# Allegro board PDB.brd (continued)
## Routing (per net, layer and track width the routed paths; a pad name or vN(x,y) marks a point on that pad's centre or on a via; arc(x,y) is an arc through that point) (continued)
P12V_RISER4: length 10.2
  TOP w0.254: PU14.2 125.52,56.23 125.67,56.38 128.02,56.38 R207.1 ; v1(123.28,56.12) 123.02,56.38 121.1,56.38 120.95,56.23 PU13.2
  BOTTOM w0.254: v1(123.28,56.12) 123.54,56.38 124.25,56.38 R206.1
  vias: v1(119.46,52.49) v1(119.46,51.48) v1(119.46,50.46) v1(119.51,49.42) v1(119.63,48.27) v1(120.47,52.49) v1(120.47,51.48) v1(120.47,50.46) v1(120.5,49.34) v1(120.6,48.3) v1(121.49,51.48) v1(121.49,50.46) v1(121.51,49.34) v1(121.54,48.27) v1(122.05,52.47) v1(122.5,51.48) v1(122.5,50.46) v1(122.56,49.29) v1(123.19,54.62) v1(123.25,53.31) v1(123.52,52.49) v1(123.52,51.48) v1(123.52,50.46) v1(124.54,52.49) v1(124.54,51.48) v1(124.54,50.46) v1(125.55,52.49) v1(125.55,51.48) v1(126.62,52.47) v1(126.62,51.45) v1(127.94,55.06) v1(127.94,54.05) v1(141.99,52.72) v1(142.62,54.62) v1(142.62,53.61) v1(148.18,52.44) v1(148.26,53.86) v1(149.86,54.62) v1(149.86,53.48) v1(149.86,52.47) v1(160.25,51.22) v1(163.25,51.22) v1(164.45,50.05) v1(164.82,47.56) v1(166.75,47.51) v1(168.15,49.8) v1(170.56,50.84) v1(172.85,44.97) v1(178.31,44.47) v1(179.83,44.47) v1(180.85,44.47) v1(182.12,44.47) v1(183.14,44.47)
P12V_RISER5: length 11.8
  TOP w0.254: PU15.2 124.51,91.66 124.36,91.8 124.36,94.38 124.71,94.73 125.36,94.73 R211.1 ; v1(124.62,89.26) 124.36,89 124.36,87.08 124.51,86.93 PU16.2
  BOTTOM w0.254: v1(124.62,89.26) 124.36,89.52 124.36,90.48 R210.1
  vias: v1(125.68,89.23) v1(126.7,89.23) v1(127.79,89.23) v1(128.4,91.45) v1(128.42,90.16) v1(128.42,89.35) v1(128.4,87.01) v1(128.5,88.52) v1(129.31,89.6) v1(129.26,88.41) v1(129.51,87.63) v1(129.51,86.61) v1(129.74,88.97) v1(130.05,92.34) v1(130.18,93.28) v1(130.53,88.52) v1(130.53,87.63) v1(130.53,86.61) v1(130.56,92.75) v1(130.56,91.71) v1(130.56,89.17) v1(131.14,93.08) v1(131.14,92.32) v1(131.55,87.63) v1(131.7,86.63) v1(131.95,93.11) v1(131.95,92.34) v1(132.11,88.2) v1(132.56,87.63) v1(132.69,86.55) v1(133.58,87.63) v1(133.63,86.55) v1(133.73,89.04) v1(138.33,87.29) v1(139.52,87.26) v1(140.64,92.6) v1(140.56,87.26) v1(142.57,88.33) v1(142.77,86.98) v1(143.71,86.98) v1(143.76,93.04) v1(144.17,91.12) v1(146.69,89.8) v1(147.07,90.69) v1(147.19,92.98) v1(148.34,91.45) v1(148.34,90.69) v1(148.34,89.8) v1(158.24,85.74) v1(159.26,85.74) v1(160.27,85.74) v1(161.29,85.74) v1(162.31,85.74)
P12V_STBY: length 46.1
  TOP w0.381: R180.1 110.03,6.67 v1(110.16,6.54) ; R200.1 158.86,26.58 v1(159.11,26.32)
  VCC1 w0.381: v1(170.59,112.41) 170.92,112.41 172.92,110.4 172.92,109.74 172.03,108.85 168.96,108.85 168.29,108.18 168.29,106.2 167.51,105.42 167.51,100.22 165.34,98.04 159.77,98.04 v1(158.32,99.49)
  BOTTOM w0.305: v1(170.59,112.41) 170.48,112.31 PR1708.1
  BOTTOM w0.381: v1(169.78,25.51) 168.97,26.32 v1(159.11,26.32) ; PC851.1 169.63,24.67 v1(169.78,24.82) ; PR708.1 163.07,12.84 v1(163.58,12.33)
  vias: v1(110.16,5.53) v1(111.18,6.54) v1(111.18,5.53) v1(112.19,6.54) v1(112.19,5.53) v1(113.21,6.54) v1(113.21,5.53) v1(157.63,100.89) v1(157.63,100.18) v1(157.63,99.49) v1(158.29,100.89) v1(158.32,100.18) v1(169.16,48.78) v1(169.93,47.51) v1(169.93,46.5) v1(170.31,12.21) v1(170.5,25.51) v1(170.5,24.85) v1(171.45,11.57) v1(171.45,10.68) v1(173.99,83.96) v1(173.99,83.2) v1(173.99,82.44)
P12V_SW_PSU: length 134.3
  TOP w0.254: PU13.1 120.95,56.89 121.08,56.76 123.03,56.76 v1(123.28,57.01) ; PU17.1 154.1,68.42 155.92,68.42 156.1,68.59 156.1,71.07 v1(155.95,71.22) ; R182.2 135,24.97 132.72,24.97 132.59,25.1 PU10.1 ; v1(130.34,25.22) 130.1,24.97 128.14,24.97 128.02,25.1 PU11.1 ; PU15.1 123.85,91.66 123.98,91.78 123.98,94.53 124.56,95.11 125.27,95.11 R209.2 ; v1(123.73,89.26) 123.98,89.01 123.98,87.06 123.85,86.93 PU16.1 ; PU14.1 125.52,56.89 125.65,56.76 127.94,56.76 R203.2
  TOP w0.381: R198.1 168.13,99.44 165.51,96.81 165.51,93.26 v1(163.96,91.71) ; PR25.1 169.56,36.84 146.94,36.84 145.29,35.19 137.97,35.19 136.47,33.7 ; 112.52,31.51 112.65,31.38 PR1045.1 ; PR1048.1 109.75,31.41
  BOTTOM w0.254: v1(123.73,89.26) 123.9,89.43 123.9,90.44 123.67,90.67 R208.2 ; R201.2 131.5,25.28 131.27,25.05 130.52,25.05 v1(130.34,25.22) ; v1(155.95,71.22) 156.06,71.33 156.06,73.76 157.06,74.77 176.97,74.77 C96.1 177.31,74.82 178.07,74.82 C50.1 178.59,74.67 179.81,74.67 U18.8 ; v1(123.28,57.01) 123.45,56.83 124.21,56.83 124.44,57.07 R202.2
  BOTTOM w0.381: v1(151.51,82.44) 152.13,83.05 153.44,83.05 162.09,91.71 v1(163.96,91.71)
  vias: v1(101.88,80.28) v1(101.96,76.06) v1(101.98,75.2) v1(101.98,64.66) v1(101.98,63.9) v1(101.96,62.93) v1(101.98,40.27) v1(101.98,39.13) v1(102.21,82.16) v1(102.82,75.07) v1(103,39.64) v1(103.12,79.44) v1(103.12,76.06) v1(103.12,74.23) v1(103.12,71.9) v1(103.12,70.98) v1(103.12,68.52) v1(103.12,65.27) v1(103.12,63.31) v1(103.23,45.76) v1(103.25,59.65) v1(103.25,48.73) v1(103.38,82.16) v1(103.38,56.99) v1(103.38,51.14) v1(103.38,44.34) v1(103.48,54.98) v1(103.5,53.99) v1(103.48,53.02) v1(103.89,39.64) v1(104.11,43.47) v1(104.11,42.2) v1(104.39,79.44) v1(104.39,76.06) v1(104.39,74.23) v1(104.39,68.52) v1(104.39,65.27) v1(104.39,63.31) v1(104.52,71.13) v1(104.52,59.65) v1(104.5,54.98) v1(104.5,53.02) v1(104.52,48.73) v1(104.65,82.16) v1(104.65,56.99) v1(104.65,51.14) v1(104.78,78.25) v1(104.9,39.64) v1(105.54,68.52) v1(105.66,65.27) v1(105.66,63.31) v1(105.66,54.98) v1(105.66,53.02) v1(105.79,76.19) v1(105.79,74.23) v1(105.92,71.19) v1(106.05,78.25) v1(106.17,82.36) v1(106.93,65.27) v1(106.93,63.31) v1(106.93,54.98) v1(106.93,53.02) v1(107.19,78.25) v1(107.19,71.19) v1(107.31,76.19) v1(107.31,74.23) v1(107.44,82.36) v1(108.2,54.98) v1(108.2,53.02) v1(108.58,78.25) v1(108.56,65.19) v1(108.56,63.24) v1(108.92,76.21) v1(108.92,74.26) v1(108.99,46.32) v1(109.45,44.87) v1(109.45,43.6) v1(109.45,42.33) v1(109.47,54.98) v1(109.47,53.02) v1(109.47,39.64) v1(109.98,65.19) v1(109.98,63.24) v1(110.34,76.21) v1(110.34,74.26) v1(110.36,77.87) v1(110.36,75.33) v1(110.62,64.28) v1(111.1,54.9) v1(111.1,52.95) v1(111.91,49.21) v1(111.89,48.48) v1(112.52,54.9) v1(112.52,52.95) v1(116.97,91.45) v1(116.97,90.44) v1(116.97,89.42) v1(117.09,93.49) v1(117.09,92.47) v1(117.98,93.49) v1(117.98,92.47) v1(117.98,91.45) v1(117.98,90.44) v1(117.98,89.42) v1(117.98,88.41) v1(118.62,59.87) v1(118.62,58.85) v1(118.62,57.84) v1(119,93.49) v1(119,92.47) v1(119,91.45) v1(119,90.44) v1(119,89.42) v1(119,88.41) v1(119,87.52) v1(119.63,63.67) v1(119.63,62.65) v1(119.63,61.76) v1(119.63,60.75) v1(119.89,89.68) v1(119.89,87.01) v1(119.89,86.25) v1(120.02,93.49) v1(120.02,92.47) v1(120.02,91.45) v1(120.02,90.44) v1(120.02,87.9) v1(120.32,98.01) v1(120.32,96.99) v1(120.4,95.95) v1(120.6,89.23) v1(120.65,63.67) v1(120.65,62.65) v1(120.65,61.76) v1(120.65,60.75) v1(121.03,93.99) v1(121.34,98.01) v1(121.34,96.99) v1(121.41,95.95) v1(121.62,89.23) v1(121.67,63.67) v1(121.67,62.65) v1(121.67,61.76) v1(122.05,93.99) v1(122.05,60.85) v1(122.35,98.01) v1(122.35,96.99) v1(122.43,95.95) v1(122.63,89.23) v1(122.56,63.67) v1(122.68,61.76) v1(122.81,62.65) v1(123.06,93.99) v1(123.19,58.82) v1(123.28,60.01) v1(123.57,63.67) v1(123.7,61.76) v1(123.7,60.75) v1(123.83,62.65) v1(124.71,61.76) v1(124.71,60.75) v1(124.84,63.51) v1(124.84,62.65) v1(125.73,61.76) v1(125.78,62.78) v1(125.86,63.51) v1(126.62,60.85) v1(126.75,61.76) v1(126.8,62.78) v1(126.87,63.51) v1(127.48,31.08) v1(127.51,29.73) v1(127.56,62.78) v1(127.56,61.76) v1(127.56,60.75) v1(127.89,63.51) v1(127.88,28.99) v1(128.4,31.26) v1(128.5,30.19) v1(128.57,62.78) v1(128.57,61.76) v1(128.57,60.75) v1(129.01,31.97) v1(129.46,60.62) v1(129.46,59.6) v1(129.46,58.59) v1(129.51,31.21) v1(129.51,30.19) v1(129.51,29.17) v1(130.02,31.97) v1(130.3,27.98) v1(130.3,26.94) v1(130.53,31.21) v1(130.53,30.19) v1(130.53,29.17) v1(130.61,60.87) v1(130.61,59.86) v1(131.06,32.02) v1(131.55,31.21) v1(131.55,30.19) v1(131.55,29.17) v1(132.38,28.99) v1(132.56,31.21) v1(132.56,30.19) v1(133.1,32.02) v1(133.58,31.21) v1(133.58,30.19) v1(133.58,29.17) v1(134.54,31.99) v1(134.59,31.21) v1(134.59,30.19) v1(134.59,29.17) v1(135.43,28.39) v1(135.61,31.21) v1(135.61,30.19) v1(135.61,29.17) v1(136.02,32.02) v1(136.35,29.48) v1(136.4,28.72) v1(136.63,31.21) v1(136.63,30.19) v1(151.1,73.04) v1(151.1,72.28) v1(151.1,71.52) v1(151.1,70.75) v1(151.1,69.99) v1(151.1,69.23) v1(151.1,68.47) v1(151.1,67.71) v1(151.1,66.94) v1(151.87,73.04) v1(151.87,72.28) v1(151.87,71.52) v1(151.87,70.75) v1(151.87,69.99) v1(151.87,69.23) v1(151.89,68.47) v1(151.87,67.71) v1(151.87,66.94) v1(151.87,66.18) v1(152.63,73.04) v1(152.63,72.28) v1(152.63,71.52) v1(152.63,70.75) v1(152.7,66.13) v1(152.7,65.37) v1(153.39,73.04) v1(153.39,72.28) v1(153.39,71.52) v1(153.39,70.75) v1(153.47,66.13) v1(153.47,65.37) v1(154.15,73.04) v1(154.15,72.28) v1(154.15,71.52) v1(154.15,70.75) v1(154.23,66.13) v1(154.23,65.37) v1(154.91,72.28) v1(154.91,71.52) v1(154.91,70.75) v1(154.99,66.13)
ADM1278_ADR1: length 3.9
  TOP w0.203: v1(114.12,20.45) 114.11,20.44 113.69,20.44 113.31,20.81 PU12.7
  BOTTOM w0.216: v1(114.12,20.45) 114.12,19.95 114.3,19.78 v2(114.3,19.62) 114.3,19.47 113.59,18.76 R11.2
ADM1278_ADR2: length 3.9
  TOP w0.216: PU12.8 114.23,21.29 114.3,21.22 v1(114.4,21.22)
  BOTTOM w0.216: v1(114.4,21.22) 114.4,21.17 114.96,20.61 114.96,18.78 R12.1
AT24C64_ADD0: length 7.6
  TOP w0.216: v3(174.09,91.68) 172,91.68 171.66,92.02 R118.2 171.03,91.61 169.65,91.61 169.37,91.88 R119.1 U3.1
AT24C64_ADD1: length 4.9
  TOP w0.216: R120.2 171.66,93.16 171.37,92.88 v1(169.77,92.88) 169.37,93.28 R121.1 U3.2
AT24C64_ADD2: length 5.8
  TOP w0.216: U3.3 R123.1 169.37,95.01 v3(170.66,96.3) 171.66,95.3 R122.2
BMC_NODE_ID_0: length 64.4
  TOP w0.216: C134.1 v1(18.16,89.22) L2.1
  BOTTOM w0.216: J5.3 64.45,107.52 64.45,105.59 63.33,104.47 24.46,104.47 23.13,103.13 23.13,91.65 21.3,89.83 18.77,89.83 v1(18.16,89.22)
BMC_NODE_ID_0_R: length 2.9
  TOP w0.216: J8.3 18.16,84.94 L2.2
BMC_NODE_ID_1: length 61.8
  TOP w0.216: L12.2 v1(16.89,89.24) C145.1
  BOTTOM w0.216: J5.4 61.98,104.89 24.29,104.89 22.71,103.31 22.71,91.83 21.13,90.25 17.89,90.25 v1(16.89,89.24)
BMC_NODE_ID_1_R: length 5.4
  TOP w0.216: J8.4 17.27,83.83 17.27,87.35 L12.1
BMC_NODE_ID_2: length 56.6
  TOP w0.216: L16.2 v1(8,89.24) C139.1
  VCC1 w0.213: v1(8,89.24) 8,89.32 8.47,89.79 12.51,89.79 13.86,91.14 13.86,93.44 16.28,95.86 16.28,97.83 23.86,105.4 52.49,105.4 J5.14
BMC_NODE_ID_2_R: length 5.7
  TOP w0.216: L16.1 8,86.81 9.17,85.64 9.17,83.79 J8.14
BMC_NODE_ID_3: length 57.5
  TOP w0.216: 6.73,89.17 L6.1 6.71,88.56 v1(6.71,89.14) 6.73,89.17 ; 6.73,89.17 C129.1
  VCC1 w0.213: v1(6.71,89.14) 6.71,89.28 8.05,90.62 10.59,90.62 11.3,91.33 11.3,92.06 14.2,94.97 14.2,97.4 23.04,106.24 41.72,106.24 44.87,109.39 50.58,109.39 J5.15
BMC_NODE_ID_3_R: length 3.1
  TOP w0.216: L6.2 6.75,87.72 6.75,85.37 J8.15
BMC_NODE_ID_4: length 61.9
  TOP w0.216: C138.1 v1(5.46,89.17) L17.2
  VCC1 w0.213: v1(5.46,89.17) 5.74,89.17 7.42,90.85 7.42,91.58 8.06,92.22 10.37,92.22 10.87,92.22 13.79,95.14 13.79,97.57 22.87,106.65 41.55,106.65 44.7,109.8 51.5,109.8 52.45,108.86 52.45,107.36 J5.16
BMC_NODE_ID_4_R: length 6.8
  TOP w0.216: L17.1 v1(5.46,86.15)
  BOTTOM w0.216: J8.16 7.26,83.89 7.26,85.59 6.71,86.15 v1(5.46,86.15)
BMC_NODE_ID_5: length 55.8
  TOP w0.216: L7.1 C128.1 4.58,89.89 4.72,90.03 4.72,92.22 7.06,94.55 12.45,94.55 14.91,97.01 v1(14.91,97.25)
  VCC1 w0.213: v1(14.91,97.25) 15.11,97.25 23.68,105.82 42.03,105.82 44.65,108.44 J5.17
BMC_NODE_ID_5_R: length 2.9
  TOP w0.216: J8.17 4.19,84.91 L7.2
CSOUT_N: length 5.6
  TOP w0.216: R164.2 113.61,30.57 v4(113.79,30.75)
  BOTTOM w0.216: C60.1 R167.1 113.77,30.73 v4(113.79,30.75) 114.71,31.67 U19.2
CSOUT_P: length 8.9
  BOTTOM w0.216: U19.3 116.38,32.32 116.87,32.81 116.87,33.42 116.33,33.95 115.34,33.95 v2(114.96,34.33) 114.58,33.95 113.18,33.95 113.03,33.8 C59.1 R166.1 R165.2
EMC1413_ADDR: length 3.3
  TOP w0.216: v1(98.42,100.09) 98.42,100.75 98.11,101.06 U2.7
  BOTTOM w0.216: v1(98.42,100.09) 97.94,100.57 R124.2
EMC1413_ALERT_N: length 5.6
  TOP w0.216: v1(99.64,100.6) 99.29,100.6 98.32,101.56 U2.8
  BOTTOM w0.216: R46.2 98.65,101.59 v1(99.64,100.6)
EN_HSC_IN: length 102.7
  TOP w0.216: v1(148.23,35.89) 148.64,35.89 R212.1 149.46,34.43 R183.1 ; U1.6 105.62,105.64 v1(104.9,104.92)
  BOTTOM w0.216: R185.2 104.78,105.04 v1(104.9,104.92) 105.54,104.28 105.54,101.8 105.99,101.35 105.99,92.14 116.57,81.55 116.57,76.05 123.45,69.17 136.9,69.17 145.63,60.44 145.63,52.33 149.44,48.52 149.44,37.19 148.23,35.98 v1(148.23,35.89)
EN_HSC_IN_R: length 1.7
  TOP w0.216: U12.2 148.08,33.29 148.23,33.44 v1(148.31,33.44) 148.34,33.44 148.51,33.27 R183.2
EN_HSC_P2V_IN_N: length 14.9
  VCC1 w0.213: J20.1 121.28,20.08 v1(119.84,20.08)
  BOTTOM w0.216: v1(119.84,20.08) 119.94,19.99 119.94,19.05 119.4,18.51 117.02,18.51 116.59,18.94 116.59,19.41 116.2,19.8 Q19.5 Q19.6 115.7,20.62 115.7,22.49 115.82,22.62 R158.1 R157.2
EN_HSC_P12V_IN: length 4.6
  TOP w0.254: PR1014.1 R13.2 119.13,19.17 v1(119.25,19.29)
  BOTTOM w0.216: Q19.3 118.88,19.15 119.02,19.29 v1(119.25,19.29)
EN_HSC_P12V_IN_BUF: length 2.1
  TOP w0.216: R184.1 145.08,34.58 v1(145.61,34.58) U12.4
EN_HSC_P12V_IN_BUF_R1: length 41.4
  TOP w0.216: R184.2 143.11,33.92 142.6,34.43 v1(142.49,34.43)
  BOTTOM w0.216: v1(142.49,34.43) 140.61,34.43 138.6,36.45 126.51,36.45 121.12,31.06 121.12,27.1 119.84,25.82 119.84,21.27 118.36,19.8 Q19.2 117.47,19.8 116.19,21.09 R163.1
EN_HSC_P12V_STBY: length 3.8
  TOP w0.216: U20.4 105.8,5.02 105.93,5.15 v1(106.4,5.15) 106.91,5.65 C107.1 R152.2 R153.1
EN_P3V3_D1G2: length 3.8
  TOP w0.216: PQ2.5 166.64,33.92 PR23.2 PR24.1 166.76,33.27 v1(167.13,33.27) PQ2.6
EN_P3V3_D2: length 2.9
  TOP w0.216: PR26.1 171.06,34.57 170.83,34.57 v1(170.32,35.08) 169.81,34.57 PQ2.3 169.73,35.49 PR25.2
EN_P3V3_G1: length 2.4
  TOP w0.216: PR22.2 168.94,35.57 v1(168.94,35.02) 168.94,34.28 169.29,33.92 PQ2.2
EN_P3V3_GATE: length 5.2
  TOP w0.381: PR26.2 171.75,35.37 v1(171.78,35.37) PC34.1 172.64,36.23 PC28.2 174.68,36.23 175.01,35.9 PQ3.4
FAN_OC_ALERT: length 8.5
  BOTTOM w0.216: R4.1 186.99,81.66 v2(187.3,81.35) 187.3,81.09 186.29,80.08 R29.1 186.29,79.64 186.06,79.41 R145.2 185.1,78.77 R147.1 185.04,78.46 184.08,77.5 183.65,77.5 183.64,77.51 Q16.5
FAN_OC_ALERT_N: length 3.6
  BOTTOM w0.216: Q2.6 186.2,86.62 186.82,87.24 v2(187.35,87.24) 187.4,87.19 R3.2
FAN_OC_ALERT_R: length 5.2
  BOTTOM w0.216: R4.2 186.19,82.78 185.55,83.42 Q2.2 Q2.5 185.55,87.06 v2(185.32,87.29)
FAN_OC_ALERT_R1_N: length 4.4
  BOTTOM w0.216: R6.1 183.65,84.7 v2(182.54,84.7) 182.54,84 182.67,83.88 Q2.3
FAN_OC_ALERT_R_N: length 106.9
  TOP w0.216: v1(111.46,112.51) 111,112.05 111,107.2 111.91,106.29 U1.20
  VCC1 w0.213: v1(111.46,112.51) 111.61,112.66 141.99,112.66 144.27,110.38 144.27,100.6 147.19,97.68 155.96,97.68 156.54,97.09 175.37,97.09 175.42,97.14 v1(176.2,97.14)
  BOTTOM w0.216: R10.2 R3.1 187.69,85.16 187.96,85.43 187.96,87.62 185.75,89.83 180.06,89.83 176.2,93.69 v1(176.2,97.14)
FAN_OC_CLEAR: length 115.3
  TOP w0.216: v1(110.21,112.49) 110.44,112.26 110.44,104.48 108.34,102.39 U1.11
  VCC1 w0.213: v1(110.21,112.49) 110.8,113.08 142.16,113.08 144.69,110.55 144.69,100.77 147.37,98.09 156.13,98.09 156.7,97.53 175.21,97.53 v1(175.67,97.98)
  BOTTOM w0.216: Q16.2 179.58,77.51 R20.1 177.4,77.25 v2(176.15,78.5) 175.01,79.64 175.01,97.32 v1(175.67,97.98)
HS_P12V_RSEN: length 32.6
  TOP w0.254: PU21.2 89.6,60.91 89.45,61.06 89.45,63.41 PR1029.2 ; R189.2 91.39,40.31 89.63,40.31 89.45,40.49 89.45,42.84 R139.2 ; PR1031.2 89.45,77.13 89.45,74.78 89.6,74.63 PU19.2 ; PR1027.2 89.45,49.7 89.45,47.35 89.6,47.2 91.34,47.2 ; PU20.2 89.6,67.77 89.45,67.92 89.45,70.27 PR1030.2 ; PR1032.2 89.45,83.86 89.45,81.64 89.6,81.49 PU18.2 ; PU22.2 89.6,54.06 89.45,54.2 89.45,56.56 PR1028.2
  vias: v1(91.14,79.21) v1(91.14,78.45) v1(91.14,77.69) v1(91.14,76.93) v1(91.14,72.35) v1(91.14,71.59) v1(91.14,70.83) v1(91.14,70.07) v1(91.14,65.5) v1(91.14,64.73) v1(91.14,63.97) v1(91.14,63.21) v1(91.14,58.64) v1(91.14,57.88) v1(91.14,57.11) v1(91.14,56.35) v1(91.14,51.78) v1(91.14,51.02) v1(91.14,50.26) v1(91.14,49.49) v1(91.14,44.92) v1(91.14,44.16) v1(91.14,43.4) v1(91.14,42.64) v1(91.24,37.99) v1(92.15,79.21) v1(92.15,78.45) v1(92.15,77.69) v1(92.15,76.93) v1(92.15,72.35) v1(92.15,71.59) v1(92.15,70.83) v1(92.15,70.07) v1(92.15,65.5) v1(92.15,64.73) v1(92.15,63.97) v1(92.15,63.21) v1(92.15,58.64) v1(92.15,57.88) v1(92.15,57.11) v1(92.15,56.35) v1(92.15,51.78) v1(92.15,51.02) v1(92.15,50.26) v1(92.15,49.49) v1(92.15,44.92) v1(92.15,44.16) v1(92.15,43.4) v1(92.15,42.64) v1(92.25,37.99) v1(95.53,81.24) v1(95.53,75.4) v1(95.53,69.56) v1(95.53,63.72) v1(95.53,57.88) v1(95.53,52.03) v1(95.53,46.19) v1(95.53,40.35) v1(96.55,82.26) v1(96.55,80.23) v1(96.55,76.42) v1(96.55,74.39) v1(96.55,70.58) v1(96.55,68.54) v1(96.55,64.73) v1(96.55,62.7) v1(96.55,58.89) v1(96.55,56.86) v1(96.55,53.05) v1(96.55,51.02) v1(96.55,47.21) v1(96.55,45.18) v1(96.55,41.37) v1(96.55,39.33) v1(97.56,81.24) v1(97.56,75.4) v1(97.56,69.56) v1(97.56,63.72) v1(97.56,57.88) v1(97.56,52.03) v1(97.56,46.19) v1(97.56,40.35)
HSC_P12V_AGND: length 17.9
  TOP w0.216: PU12.22 v1(111.31,27.4)
  TOP w0.305: v1(107.24,23.59) 107.16,23.59 106.73,23.15 PC1018.2 ; v1(108.31,18.84) 107.75,18.28 PC1013.2 PR1033.2 ; PR1037.2 PC1015.2 107.78,20.04 v1(108.33,20.59) ; PC1020.2 106.76,26.13 v1(107.21,25.67)
  TOP w0.381: PC1017.2 105.69,21.27 v1(105.44,21.02) ; PC1016.2 113.41,17.77 v1(112.88,17.24) 112.88,17.32 PC1010.2
  TOP w0.457: PC1011.2 117.6,23.13 117.91,22.82 v1(117.91,22.32) 117.6,22.01 PR1010.2 ; PC1012.2 109.04,17.85 v1(109.4,17.49) 110.13,17.49 PC109.2 110.45,17.8 PC1014.2 ; PR1050.2 PC1023.2 v1(111.68,29.61)
  BOTTOM w0.381: 113.28,16.52 113.67,16.52 114.55,17.41 R12.2
  vias: v1(110.79,23.84) v1(112.06,25.11) v1(112.06,22.57) v1(113.33,23.84) v2(110.03,23.18)
HSC_P12V_ALERT_N: length 2.8
  TOP w0.216: PU12.13 115.77,24.09 v3(116.05,24.37) 117.18,24.37 PR10153.2
HSC_P12V_CSOUT: length 2.5
  TOP w0.216: PU12.19 112.81,27 113.49,27.68 v1(113.72,27.68) 113.72,28.19 R164.1
HSC_P12V_DN: length 84
  TOP w0.254: v1(108.33,24.82) 108.46,24.82 108.7,24.59 PU12.27 ; PR1032.1 89.41,85.12 89.41,85.46 v1(89.56,85.61) ; PR1029.1 89.41,64.68 89.41,65.01 v1(89.56,65.17) ; v1(89.56,44.59) 89.41,44.44 89.41,44.1 R139.1 ; v1(89.56,58.31) 89.41,58.16 89.41,57.82 PR1028.1 ; v1(105.13,25.06) 105.13,25.01 105.26,24.88 105.59,24.88 PR1042.1 PC1020.1 ; v1(89.56,51.45) 89.41,51.3 89.41,50.96 PR1027.1 ; PR1031.1 89.41,78.39 89.41,78.73 v1(89.56,78.88) ; PR1030.1 89.41,71.53 89.41,71.87 v1(89.56,72.02)
  BOTTOM w0.254: v1(108.33,24.82) 108.21,24.7 107.4,24.7 107.3,24.81 105.38,24.81 v1(105.13,25.06) 104.93,24.86 103.97,24.86 103.25,25.57 103.25,27.83 98.41,32.68 96.68,32.68 92.13,37.23 90.2,37.23 89.41,38.02 89.41,44.44 v1(89.56,44.59) 89.41,44.74 89.41,51.3 v1(89.56,51.45) 89.41,51.6 89.41,58.16 v1(89.56,58.31) 89.41,58.46 89.41,65.01 v1(89.56,65.17) 89.41,65.32 89.41,71.87 v1(89.56,72.02) 89.41,72.18 89.41,78.73 v1(89.56,78.88) 89.41,79.03 89.41,85.46 v1(89.56,85.61)
HSC_P12V_DP: length 84.6
  TOP w0.254: v1(88.87,85.61) 89.03,85.46 89.03,85.12 PR1018.1 ; PR1020.1 89.03,50.96 89.03,51.3 v1(88.87,51.45) ; PR1015.1 89.03,64.68 89.03,65.01 v1(88.87,65.17) ; v1(88.87,78.88) 89.03,78.73 89.03,78.39 PR1017.1 ; v1(88.87,72.02) 89.03,71.87 89.03,71.53 PR1016.1 ; v1(105.11,24.25) 105.11,24.27 105.23,24.4 105.59,24.4 PR1041.1 PC1018.1 ; v1(108.33,24.16) 108.4,24.09 PU12.28 ; v1(88.87,44.59) 89.03,44.44 89.03,44.1 R58.1 ; v1(88.87,58.31) 89.03,58.16 89.03,57.82 PR1019.1
  BOTTOM w0.254: v1(88.87,85.61) 89.03,85.46 89.03,79.03 v1(88.87,78.88) 89.03,78.73 89.03,72.18 v1(88.87,72.02) 89.03,71.87 89.03,65.32 v1(88.87,65.17) 89.03,65.01 89.03,58.46 v1(88.87,58.31) 89.03,58.16 89.03,51.6 v1(88.87,51.45) 89.03,51.3 89.03,44.74 v1(88.87,44.59) 89.03,44.44 89.03,37.86 90.04,36.84 91.97,36.84 96.52,32.3 98.25,32.3 102.87,27.68 102.87,25.42 103.81,24.47 104.88,24.47 v1(105.11,24.25) 105.28,24.42 107.14,24.42 107.25,24.31 108.18,24.31 v1(108.33,24.16)
HSC_P12V_EN: length 6.6
  TOP w0.216: v3(115.16,19.65) 115.67,20.16 PR1014.2 116.49,20.18 PR1011.2 PR1010.1 116.49,23.08 PC1011.1 115.62,23.13 115.16,23.59 PU12.12
HSC_P12V_FAULT_N: length 153.5
  TOP w0.216: PU12.6 112.81,20.7 114.35,19.17 PR10154.2 114.81,18.42 115.7,17.54 116.61,17.54 117.03,17.96 v1(117.16,17.96) ; v1(106.93,99.84) 107.06,99.96 108.65,99.96 109.68,100.99 109.68,101.68 109.68,101.68 109.68,101.94 111,103.27 112.7,103.27 112.93,103.04 U1.15
  BOTTOM w0.216: v1(117.16,17.96) 117.23,18.02 119.51,18.02 120.36,18.87 120.36,25.64 121.54,26.82 121.54,30.88 126.69,36.03 138.1,36.03 140.34,33.8 145.8,33.8 147.19,35.19 148.46,35.19 149.86,36.59 149.86,48.7 146.05,52.51 146.05,60.62 137.08,69.59 123.62,69.59 116.99,76.22 116.99,81.73 106.41,92.31 106.41,99.31 v1(106.93,99.84)
HSC_P12V_GATE: length 0.6
  TOP w0.305: PU12.24 v1(109.73,26.39)
  vias: v2(108.43,29.48)
HSC_P12V_GATE1: length 3
  TOP w0.508: PQ101.4 v1(101.85,48.11)
  BOTTOM w0.508: v1(101.85,48.11) 101.83,48.09 PR102.1
HSC_P12V_GATE2: length 2.8
  TOP w0.508: PQ102.4 v1(101.85,42.27)
  BOTTOM w0.508: PR103.1 101.83,42.3 v1(101.85,42.27)
HSC_P12V_GATE3: length 2.7
  TOP w0.457: PQ103.4 101.58,83.16 v1(101.59,83.17)
  BOTTOM w0.508: PR104.1 101.46,83.3 v1(101.59,83.17)
HSC_P12V_GATE4: length 2.8
  TOP w0.508: v1(101.85,71.48) PQ104.4
  BOTTOM w0.508: PR105.1 101.83,71.51 v1(101.85,71.48)
HSC_P12V_GATE5: length 2.9
  TOP w0.508: PQ105.4 101.82,77.32 v1(101.85,77.36)
  BOTTOM w0.508: v1(101.85,77.36) 101.83,77.38 PR106.1
HSC_P12V_GATE6: length 2.8
  TOP w0.508: PQ106.4 v1(101.83,65.64)
  BOTTOM w0.508: PR101.1 v1(101.83,65.64)
HSC_P12V_GATE7: length 3
  TOP w0.508: v1(101.85,53.95) PQ107.4
  BOTTOM w0.508: PR1049.1 101.83,53.93 v1(101.85,53.95)
HSC_P12V_GATE8: length 3
  TOP w0.508: PQ108.4 v1(101.85,59.8)
  BOTTOM w0.508: v1(101.85,59.8) 101.83,59.77 PR107.1
HSC_P12V_ISET: length 6
  TOP w0.216: PU12.3 111.31,19.56 v1(111,19.24) 111.43,18.81 PC1014.1
  BOTTOM w0.216: v1(111,19.24) 111.02,19.27 111.18,19.27 111.4,19.5 111.4,19.6 112.16,20.35 PR1035.2 PR1036.1
HSC_P12V_ISTART: length 6.4
  TOP w0.216: PU12.4 111.81,19.7 v1(112.29,19.22) 112.39,19.12 PC1010.1
  BOTTOM w0.216: PR109.1 112.29,19.76 v1(112.29,19.22) 112.29,19.15 PR108.2
HSC_P12V_MON: length 3.3
  TOP w0.254: PR1042.2 106.76,25.03 PC1019.2 108.01,25.41 108.61,25.41 108.94,25.09 PU12.26
HSC_P12V_MOP: length 3.4
  TOP w0.254: PR1041.2 106.73,24.23 PC1019.1 107.62,23.99 108.02,23.59 PU12.29
HSC_P12V_OV: length 7.4
  TOP w0.216: PR1034.2 105.61,18.96 105.73,19.08 PR1033.1 PC1013.1 107.75,19.08 109.51,20.85 PU12.32
HSC_P12V_PSET: length 5.1
  TOP w0.216: v1(109.42,19.55) 109.42,19.88 110.31,20.77 PU12.1
  TOP w0.254: PC1012.1 109.04,19.17 v1(109.42,19.55)
  BOTTOM w0.216: PR1013.1 PR1012.2 109.61,20.06 109.42,19.88 v1(109.42,19.55)
HSC_P12V_PWGIN: length 4.4
  TOP w0.216: PR1048.2 109.75,28.59 v1(110.06,28.28) 110.2,28.14 PR1050.1 PC1023.1 111.75,28.14 111.89,28.01 111.89,27.04 111.81,26.97 PU12.21
HSC_P12V_PWRGD: length 207.2
  TOP w0.216: v1(153.03,91.45) 153.03,91.33 153.47,90.9 164.41,90.9 166.07,92.55 166.07,96.41 167.59,97.93 172.59,97.93 173.61,98.95 R15.1 ; PR22.1 167.36,36.34 156.09,36.34 v1(155.7,35.96) ; R14.2 PR10152.2 115.6,28.99 116.82,28.99 118.68,27.13 v1(122.66,27.13) ; v1(99.77,7.03) v1(102.92,7.03)
  BOTTOM w0.216: Q3.G 99.25,6.25 99.77,6.77 v1(99.77,7.03) ; v1(153.03,91.45) 153.03,91.16 154.03,90.17 154.03,88.81 151.94,86.73 148.38,86.73 145.74,84.09 138.79,84.09 137.38,82.67 137.38,74.51 151.28,60.6 151.28,52.44 155.88,47.84 155.88,36.13 v1(155.7,35.96) 155.7,34.74 154.79,33.82 150.39,33.82 149.43,32.86 146.01,32.86 145.32,32.18 140.58,32.18 137.99,34.77 127.34,34.77 122.56,29.99 122.56,27.23 v1(122.66,27.13) 122.56,27.03 122.56,26.65 121.2,25.29 121.2,17.93 119.7,16.44 116.2,16.44 114.75,14.98 107.92,14.98 106.43,13.49 106.43,7.69 105.77,7.03 v1(102.92,7.03)
HSC_P12V_PWRGD_R: length 3.3
  TOP w0.216: R14.1 114.6,27.95 v1(115.01,27.55) 114.68,27.22 114.05,27.22 113.94,27.12 113.54,27.12 113.31,26.89 PU12.18
HSC_P12V_STBY_AGND: length 0.7
  TOP w0.381: C107.2 v1(108.46,5.65)
  vias: v1(102.03,3.49) v1(102.03,2.48)
HSC_P12V_STBY_FAULT_INPUT: length 4.1
  TOP w0.216: R181.1 R180.2 106.05,5.76 v1(105.26,5.76) 105.15,5.86 U20.6
HSC_P12V_STBY_GATE: length 6.2
  TOP w0.508: v1(115.29,6.34) 115.29,6.21 115.09,6.01 R50.1 114.35,6.14 Q5.4
  BOTTOM w0.508: v1(115.29,6.34) 115.29,5.83 114.04,4.59 R49.2
HSC_P12V_STBY_GATE_R: length 10.4
  TOP w0.432: U20.5 105.8,7.64 106.58,8.42 107.34,8.42 v1(107.49,8.57)
  BOTTOM w0.508: v1(107.49,8.57) 107.52,8.6 107.57,8.6 107.7,8.48 107.7,5.35 108.2,4.84 109.21,4.84 109.46,4.59 111.52,4.59 R49.1
HSC_P12V_STBY_PWRGD: length 87.9
  TOP w0.216: v1(108.84,1.92) 108.97,1.92 109.52,2.48 R171.2 109.48,3.14 109.3,3.14 108.78,2.62 C109.1 R173.1 105.15,2.93 U20.3 ; v1(150.35,32.36) 153.8,28.92 153.8,26.94 156.08,24.65 PR702.1
  BOTTOM w0.216: v1(108.84,1.92) 108.97,2.05 108.97,2.81 110.13,3.97 114.23,3.97 116.61,6.35 116.61,8.8 117.09,9.29 117.09,15.47 117.64,16.02 119.88,16.02 121.62,17.76 121.62,25.04 123.19,26.62 123.19,30.03 127.52,34.36 137.81,34.36 140.4,31.76 145.67,31.76 145.97,32.07 147.14,32.07 147.73,31.49 149.47,31.49 v1(150.35,32.36)
HSC_P12V_STBY_RSENSE: length 4.6
  TOP w0.254: R48.2 104.83,13.02 104.57,12.77 104.57,10.5 R155.1
  vias: v3(108.99,10.4)
HSC_P12V_STBY_TIMER: length 2.7
  TOP w0.381: U20.1 103.85,5.23 103.58,5.5 102.84,5.5 102.79,5.55 ; 102.79,5.55 v1(102.77,5.58) ; 102.79,5.55 C106.1
HSC_P12V_TEMP: length 4.2
  TOP w0.305: PR1047.1 107.49,27.32 PC1021.2 108.43,27.5 v3(108.43,26.68) 108.43,26.56 109.4,25.59 PU12.25
HSC_P12V_TIMER: length 3.2
  TOP w0.216: PC1016.1 113.41,19.14 v3(112.67,19.88) 112.31,20.24 PU12.5
HSC_P12V_UV: length 6.8
  TOP w0.216: PU12.31 108.94,22.59 108.71,22.37 108.71,21.73 107.82,20.84 PC1015.1 PR1037.1 106.21,20.84 105.43,20.06 v3(105.23,20.06) 105.13,19.95 PR1038.2
HSC_P12V_VCAP: length 10.3
  TOP w0.254: PU12.2 110.81,20.25 v1(110.59,20.03)
  TOP w0.305: PC109.1 110.26,19.7 v1(110.59,20.03)
  BOTTOM w0.254: PR1035.1 110.51,20.61 PR1012.1 110.41,20.21 v1(110.59,20.03) 110.59,19.72 110.32,19.45 PR108.1 110.32,17.84 110.72,17.44 111.86,17.44 v2(112.34,17.92) 112.98,17.92 113.33,17.57 R11.1
HSC_P12V_VCC: length 6.1
  TOP w0.254: PU12.30 108.59,23.09 108.2,22.7 108.2,22.11 108.02,21.93 107.22,21.93 PC1017.1
  TOP w0.381: v1(107.57,22.8) 107.16,22.39 PC1017.1
  BOTTOM w0.381: PR1039.2 107.57,22.21 107.57,22.62
  BOTTOM w0.457: 107.57,22.62 v1(107.57,22.8)
HSC_P12V_VOUT: length 2
  TOP w0.216: PU12.20 112.31,26.82 112.34,26.85 112.34,27.42 v1(112.43,27.51) 112.65,27.73 PR1045.2
I2C_ADM1278_SCL: length 4.6
  TOP w0.216: PR1043.1 117.23,27.29 v3(116.89,27.62) 116.81,27.62 114.78,25.59 PU12.16
I2C_ADM1278_SDA: length 3.2
  TOP w0.216: PR1044.1 116.66,25.29 v3(116.05,25.9) 115.25,25.09 PU12.15
I2C_BMC_MM3_R_SCL: length 23.9
  TOP w0.216: J9.5 6.68,100.98 12.64,100.98 13.34,100.98 18.16,105.8 18.16,110.89 19.18,111.9 L9.2
I2C_BMC_MM3_R_SDA: length 23.6
  TOP w0.216: J9.4 7.49,97.79 7.49,99.96 8.09,100.56 12.47,100.56 13.52,100.56 18.58,105.62 18.58,110.63 18.83,110.89 L19.1
I2C_BMC_MM3_SCL: length 52
  TOP w0.216: L9.1 C135.1 21.82,112.28 21.95,112.41 66.58,112.41 67.48,111.51 70.54,111.51 70.78,111.76 R104.2 R90.1
I2C_BMC_MM3_SDA: length 52.5
  TOP w0.216: L19.2 C140.1 21.82,110.83 22.29,110.37 26.23,110.37 27.74,111.88 66.45,111.88 67.28,111.04 70.66,111.04 70.78,110.91 R103.2 R89.1
I2C_BMC_MM8_R_SCL: length 12.7
  BOTTOM w0.216: J9.1 10.92,98.82 17.53,105.42 L8.2
I2C_BMC_MM8_R_SDA: length 14.3
  BOTTOM w0.216: J9.2 9.51,96.82 18.54,105.85 L18.1
I2C_BMC_MM8_SCL: length 287.9
  TOP w0.216: v1(123.65,24.88) 122.18,24.88 121.16,25.9 118.41,25.9 PR1043.2 ; R92.1 v1(113.02,99.84) R106.2 112.41,99.57 112.14,99.3 105.57,99.3 102.48,102.39 101.64,102.39 v1(101.48,102.55) 101.41,102.48 100.88,102.48 R115.1 ; v1(155.16,95.84) 155.31,95.69 156.44,95.69 R113.1
  BOTTOM w0.216: v1(101.48,102.55) 101.44,102.5 100.91,102.5 100.69,102.73 100.69,111.62 99.82,112.49 73.63,112.49 72.62,111.47 66.98,111.47 65.32,113.13 20.03,113.13 16.85,109.95 16.85,108.72 17.36,108.2 C137.1 L8.1 ; v1(123.65,24.88) 124.76,26 124.76,29.5 128.13,32.87 137.2,32.87 140.07,30 154.42,30 159.44,35.02 159.44,47 154.18,52.25 154.18,53.4 154.18,60.57 146.05,68.7 146.05,82.13 149.1,85.18 152.51,85.18 157.19,89.86 157.19,95.05 156.52,95.72 155.37,95.72 155.26,95.84 v1(155.16,95.84) 155.05,95.73 153.88,95.73 153.2,95.05 150.43,95.05 143.78,101.7 120.66,101.7 118.26,99.3 113.56,99.3 v1(113.02,99.84)
I2C_BMC_MM8_SDA: length 289.9
  TOP w0.216: R91.1 v1(113.03,98.31) R105.2 112.41,98.62 112.21,98.83 105.37,98.83 102.28,101.92 101.52,101.92 101.45,101.85 v1(101.44,101.85) 101.44,101.89 101.33,102.01 100.87,102.01 R116.1 ; PR1044.2 118.17,25.43 120.97,25.43 122.3,24.1 v1(123.44,24.1) ; v1(155.23,95.13) 155.28,95.18 156.39,95.18 R114.1
  BOTTOM w0.216: v1(113.03,98.31) 113.55,98.83 118.45,98.83 120.85,101.23 143.58,101.23 150.24,94.58 153.39,94.58 154.07,95.26 155.1,95.26 v1(155.23,95.13) 155.36,95.25 156.32,95.25 156.72,94.86 156.72,90.06 152.31,85.65 148.74,85.65 146.16,83.07 143.81,83.07 143.32,82.58 143.32,70.77 152.13,61.95 152.13,61.83 153.71,60.25 153.71,53.59 153.71,53.59 153.71,52.06 158.97,46.81 158.97,35.21 154.22,30.47 140.26,30.47 137.39,33.34 127.94,33.34 124.21,29.61 124.21,26.2 123.03,25.02 123.03,24.51 v1(123.44,24.1) ; v1(101.44,101.85) 101.38,101.91 100.84,101.91 100.22,102.54 100.22,111.43 99.63,112.02 73.83,112.02 72.81,111 66.78,111 65.12,112.66 20.22,112.66 19.81,112.25 19.81,108.88 19.13,108.2 C142.1 L18.2
I2C_FRU_SCL: length 11.3
  TOP w0.216: R113.2 157.95,95.7 158.47,95.7 160.45,97.68 163.32,97.68 164.19,96.81 164.19,95.65 163.5,94.96 162.51,94.96 162.32,94.77 U3.6
I2C_FRU_SDA: length 9.3
  TOP w0.216: U3.5 162.47,95.87 163.53,95.87 163.65,96 163.65,96.59 163.1,97.14 160.67,97.14 158.64,95.11 157.94,95.11 R114.2
I2C_MB_SCL: length 35.2
  TOP w0.216: L4.1 v1(13.34,89.24) C131.1 13.28,89.89 12.8,90.38 12.8,92.04 17.31,96.55 17.31,100.94 22.73,106.36 34.04,106.36 34.46,106.78 R102.2 R51.1
I2C_MB_SCL_R: length 3.2
  TOP w0.216: J8.7 14.24,85.42 13.34,86.32 L4.2
I2C_MB_SDA: length 37.2
  TOP w0.216: R54.2 R101.2 34.46,108.17 34.16,108.47 32.77,108.47 32.26,107.96 32.26,107.2 31.88,106.83 23.08,106.83 23.07,106.83 22.53,106.83 16.84,101.14 16.84,96.75 12.33,92.23 12.33,90.36 11.86,89.89 C143.1 v1(11.81,89.22) L14.2
I2C_MB_SDA_R: length 6
  TOP w0.216: L14.1 11.81,86.86 13.32,85.35 13.32,83.55 14.01,82.86 J8.8
I2C_PCA9546A_SCL: length 8
  TOP w0.216: U14.14 74.85,106.74 74.51,107.08 74.51,110.54 73.66,111.39 72.56,111.39 72.43,111.52 R90.2
I2C_PCA9546A_SDA: length 7.9
  TOP w0.216: R89.2 72.43,110.68 72.64,110.89 73.44,110.89 74.04,110.29 74.04,106.69 74.65,106.09 U14.15
I2C_PCA9555_SCL: length 10.7
  TOP w0.216: R92.2 114.95,99.33 115.29,99.33 115.54,99.59 115.54,106.34 114.3,107.59 U1.22
I2C_PCA9555_SDA: length 12.4
  TOP w0.216: U1.23 114.41,108.24 116.01,106.63 116.01,99.39 115.49,98.86 115,98.86 R91.2
I2C_PSU1_SCL: length 27.7
  TOP w0.216: R51.2 44.42,106.92 v1(45.06,106.28)
  BOTTOM w0.216: v1(45.06,106.28) 45.03,106.31 45.03,107.96 47.54,110.47 58.46,110.47 59.53,109.4 J5.7
I2C_PSU1_SDA: length 29.3
  TOP w0.216: v1(46.02,106.34) 44.97,107.39 37.17,107.39 36.63,107.94 R54.1
  BOTTOM w0.216: J5.8 59.23,106.44 58.61,107.07 58.61,109.4 58.01,110 47.98,110 46.02,108.04 v1(46.02,106.34)
I2C_PSU2_R_SCL: length 261.7
  TOP w0.216: v1(87.5,107.45) 87.49,107.43 86.94,107.43 86.76,107.62 R52.2
  VCC1 w0.213: v1(87.5,107.45) 87.42,107.37 68.85,107.37 65.34,110.87 44.26,110.87 41.11,107.72 35.73,107.72 34.71,108.74 26.53,108.74 25.51,107.72 22.43,107.72 22.19,107.47 22.17,107.47 12.73,98.03 12.73,95.58 11.6,94.45 6.96,94.45 4.85,92.34 4.85,90.31 4.43,89.9 4.43,87.6 5.12,86.91 6.68,86.91 7.16,86.43 7.16,78.75 3.65,75.24 3.65,26.49 8.99,21.14 10.67,21.14 14.4,17.42 14.4,11.47 18.59,7.28 21.56,7.28 22.09,6.75 34.44,6.75 35.59,5.6 39.57,5.6 40.72,6.75 57.89,6.75 60.7,9.57 66.99,9.57 68.77,11.34 68.77,20.22 70.44,21.89 70.44,26.71 J6.7
I2C_PSU2_R_SDA: length 255
  TOP w0.216: R55.1 86.76,106.54 87.04,106.82 v1(87.48,106.82)
  VCC1 w0.213: v1(87.48,106.82) 87.4,106.9 69.04,106.9 68.66,106.9 65.15,110.4 44.46,110.4 41.3,107.25 35.54,107.25 34.52,108.27 26.72,108.27 25.7,107.25 22.62,107.25 22.38,107 22.36,107 13.19,97.84 13.19,95.38 10.62,92.81 7.33,92.81 5.97,91.46 5.97,90.77 4.9,89.7 4.9,87.79 5.32,87.38 7.33,87.38 9.19,85.51 9.19,80.13 4.11,75.05 4.11,26.68 9.19,21.61 10.99,21.61 16.9,15.7 16.9,12.61 21.76,7.75 22.29,7.22 57.69,7.22 60.54,10.06 66.83,10.06 68.3,11.54 68.3,20.41 69.52,21.63 J6.8
I2C_PSU2_SCL: length 5.1
  TOP w0.216: U14.5 82.82,108.04 v1(83.01,108.22) 83.34,107.89 83.64,107.89 R94.2 83.67,107.78 84.3,107.15 85.47,107.15 85.96,107.64 R52.1
I2C_PSU2_SDA: length 5.5
  TOP w0.216: R55.2 85.49,106.67 84,106.67 83.67,106.35 R93.2 83.43,106.32 83.43,106.61 82.65,107.39 U14.4
I2C_PSU3_R_SCL: length 259
  TOP w0.216: v1(87.6,109.92) 87.07,109.92 86.76,110.23 R53.2
  VCC1 w0.213: J7.7 83.61,5.38 66.88,5.38 66.17,4.66 35.2,4.66 34.05,5.82 24.24,5.82 23.08,4.65 19.75,4.65 13.46,10.94 13.46,11.32 13.46,17.03 10.29,20.21 8.99,20.21 8.61,20.21 2.71,26.1 2.71,86.42 3.21,86.92 3.21,92.89 5.71,95.39 11.22,95.39 11.79,95.97 11.79,98.42 22.39,109.02 25.03,109.02 27.48,111.47 34.58,111.47 34.59,111.48 35.01,111.48 35.02,111.47 43.54,111.47 43.88,111.81 66.47,111.81 69.16,109.11 72.85,109.11 73.19,109.45 86.22,109.45 86.61,109.84 87.53,109.84 v1(87.6,109.92)
I2C_PSU3_R_SDA: length 259.5
  TOP w0.216: v1(87.6,109.26) 86.92,109.26 86.76,109.1 R56.1
  VCC1 w0.213: v1(87.6,109.26) 87.5,109.36 86.79,109.36 86.41,108.98 73.38,108.98 73.04,108.64 68.97,108.64 66.27,111.34 44.07,111.34 40.92,108.18 35.93,108.18 34.91,109.2 26.33,109.2 25.31,108.18 22.24,108.18 22.07,108.02 22.05,108.02 12.26,98.23 12.26,95.77 11.41,94.92 5.9,94.92 3.68,92.7 3.68,86.73 3.18,86.23 3.18,26.29 8.8,20.68 10.48,20.68 13.93,17.23 13.93,11.13 19.94,5.12 22.89,5.12 24.05,6.28 34.24,6.28 35.4,5.13 39.81,5.13 40.97,6.28 67.61,6.28 69.13,7.8 83.19,7.8 J7.8
I2C_PSU3_SCL: length 5.4
  TOP w0.216: R53.1 85.96,110.63 85.55,111.04 v1(85.19,111.04) 84.45,111.04 R96.2 83.55,110.27 82.62,109.34 U14.7
I2C_PSU3_SDA: length 4.8
  TOP w0.216: U14.6 82.59,108.69 82.77,108.87 R95.2 83.67,109.04 84.1,109.46 84.84,109.46 85.43,108.87 R56.2
I2C_TEMP_SENSOR_SCL: length 2.8
  TOP w0.216: U2.10 99.61,102.56 R115.2
I2C_TEMP_SENSOR_SDA: length 2.8
  TOP w0.216: R116.2 99.48,102.06 U2.9
INA301_P12V_RISER3_DN: length 12.8
  TOP w0.254: R204.2 136.32,24.6 136.72,24.6 v1(136.84,24.48)
  BOTTOM w0.254: U15.7 140.36,26.83 C42.1 140.06,26.65 139.79,26.92 139.32,26.92 C94.2 139.02,26.96 138.56,26.96 138.2,26.61 138.2,25.1 137.73,24.63 136.99,24.63 v1(136.84,24.48) 136.75,24.58 134.21,24.58 v2(134.06,24.42) 133.91,24.58 132.5,24.58 R205.2
INA301_P12V_RISER3_DP: length 12.8
  TOP w0.254: R182.1 136.31,25.06 136.73,25.06 v1(136.84,25.17)
  BOTTOM w0.254: U15.8 140.33,27.48 C40.1 139.93,27.37 139.41,27.37 C94.1 139.02,27.42 138.35,27.42 137.74,26.81 137.74,25.36 137.46,25.08 136.92,25.08 v1(136.84,25.17) 136.71,25.03 136.17,25.03 v2(135.99,25.21) 135.81,25.03 132.55,25.03 R201.1
INA301_P12V_RISER4_DN: length 9.4
  TOP w0.254: R207.2 129.26,56.39 129.66,56.39 v1(129.78,56.27)
  BOTTOM w0.254: U16.7 131.73,56.37 C41.1 131.29,56.45 130.75,56.45 C93.2 130.41,56.4 129.91,56.4 v1(129.78,56.27) 129.68,56.36 128.49,56.36 v2(128.32,56.2) 128.16,56.36 125.44,56.36 R206.2
INA301_P12V_RISER4_DP: length 9.5
  TOP w0.254: R203.1 129.24,56.85 129.67,56.85 v1(129.78,56.96)
  BOTTOM w0.254: U16.8 131.7,57.02 C39.1 131.29,56.91 130.7,56.91 C93.1 130.36,56.86 129.87,56.86 v1(129.78,56.96) 129.64,56.82 127.06,56.82 v2(126.87,57.01) 126.68,56.82 125.49,56.82 R202.1
INA301_P12V_RISER5_DN: length 19.4
  TOP w0.254: R211.2 126.59,94.74 126.99,94.74 v1(127.11,94.62)
  BOTTOM w0.254: U17.7 133.48,90.43 133.17,90.12 ; 133.17,90.12 v2(133.17,90.11) ; 133.17,90.12 132.98,89.93 131.68,89.93 C51.1 131.16,90.08 130.58,90.08 C95.2 130.18,90.13 129.58,90.13 129.03,90.68 129.03,93.69 127.98,94.74 127.23,94.74 v1(127.11,94.62) 126.98,94.76 124.74,94.76 124.33,94.35 124.33,91.71 R210.2
INA301_P12V_RISER5_DP: length 19.2
  TOP w0.254: v1(127.11,95.31) 127,95.2 126.58,95.2 R209.1
  BOTTOM w0.254: U17.8 132.83,90.71 132.51,90.39 131.83,90.39 C49.1 131.31,90.54 130.58,90.54 C95.1 130.28,90.59 129.77,90.59 129.49,90.87 129.49,93.88 128.17,95.2 127.22,95.2 v1(127.11,95.31) 127.01,95.21 125.83,95.21 v2(125.68,95.37) 125.53,95.21 124.55,95.21 123.88,94.54 123.88,91.69 R208.1
LED_P3V3_CB_N: length 1.7
  TOP w0.216: R45.2 v1(183.41,94.15) 183.41,94.88 D6.C
LED_P3V3_CB_R_N: length 2.3
  TOP w0.216: R45.1 v1(181.89,93.36) 181.19,94.06 Q4.D
LED_P3V3_STBY_N: length 2.1
  TOP w0.216: D1.C v1(101.4,2.05)
  BOTTOM w0.216: R44.1 v1(101.4,2.05)
LED_P3V3_STBY_R_N: length 1.6
  BOTTOM w0.216: R44.2 99.93,3.09 Q3.D
OC1_ALERT_N: length 10.8
  TOP w0.216: v1(145.43,21.87) 144.26,21.87 v3(144.15,21.99)
  BOTTOM w0.216: U15.6 142.75,26.18 142.95,25.98 142.95,23.31 143.3,22.96 Q13.3 145.9,22.96 R126.2 145.92,22.37 v1(145.43,21.87) U4.1
OC1_DELAY: length 14.8
  BOTTOM w0.216: R40.2 146.2,17.79 R134.1 146.08,17.67 146.08,17.24 145.69,16.85 145.08,16.85 145.07,16.85 143.82,16.85 143,17.67 142.8,17.67 142.47,18 142.47,19.17 141.55,20.08 140.21,20.08 140.08,20.21 140.08,22.39 140.44,22.75 140.44,22.75 ; 140.44,22.75 140.44,22.75 140.59,22.9 140.94,22.9 141.97,21.87 U4.6 ; 140.44,22.75 v2(140.43,22.75)
OC1_DELAY_N: length 3.1
  TOP w0.216: v1(143.29,20.17) 143.88,20.17 144.09,20.39 v3(144.32,20.39)
  BOTTOM w0.216: U4.4 142.89,20.57 v1(143.29,20.17) U5.1
OC1_DELAY_RC: length 7.3
  TOP w0.216: v1(146.48,19.52) 146.02,19.06 v3(145.47,19.06)
  BOTTOM w0.216: C47.1 145.47,21.02 146.16,21.72 D2.1 ; C47.1 145.12,20.46 145,20.57 U4.3 ; C47.1 145.48,20.44 146.15,20.44 146.46,20.13 146.46,19.55 v1(146.48,19.52) 146.18,19.22 R134.2
OC1_DELAY_RD: length 3.8
  BOTTOM w0.216: v2(150.19,17.79) R40.1 148.82,18.47 D2.3
OC1_LIMIT: length 2.9
  BOTTOM w0.216: R127.1 148.01,26.38 v2(147.96,26.43) 147.57,26.43 147.33,26.18 U15.3
OC1_OUT: length 5.1
  BOTTOM w0.216: U15.2 147.06,26.83 147.8,27.57 148.69,27.57 v2(148.72,27.55) 149,27.27 C45.1
OC1_RESET: length 5.2
  BOTTOM w0.216: U15.5 141.79,24.85 141.9,24.74 Q13.6 141.77,24.39 v2(140.41,24.39) 139.93,24.39 R130.1 R36.2
OC1_VS_R: length 16.7
  BOTTOM w0.254: R126.1 146.56,23.78 147.19,23.15 v2(147.8,23.15) 149.2,23.15 149.61,23.56 149.61,27.78 148.06,29.33 145.01,29.33 144.88,29.2 R21.1 145.26,28.46 C43.2 146.28,27.57 U15.1
OC2_ALERT_N: length 12
  BOTTOM w0.216: 134.13,55.71 133.17,55.71 U16.6 ; 134.13,55.71 134.34,55.5 134.34,52.82 134.66,52.5 Q14.3 135.68,52.5 135.71,52.47 R128.2 136.38,52.34 136.38,51.96 137,51.34 U6.1 ; 134.13,55.71 134.34,55.92 134.34,57.7 132.97,59.07 v2(132.72,59.07)
OC2_DELAY: length 8.7
  BOTTOM w0.216: U6.6 135.62,51.34 136.14,50.81 136.14,50.05 137.03,49.16 137.03,48.15 137.79,47.39 v2(137.92,47.39) 139.21,47.39 R135.1 140.21,47.75 R41.2
OC2_DELAY_N: length 2.2
  BOTTOM w0.216: U6.4 135.55,50.04 135.7,49.88 135.7,49.69 v4(135.48,49.47) 135.09,49.08 U7.1
OC2_DELAY_RC: length 8.5
  BOTTOM w0.216: v2(140.84,53.1) 140.15,52.4 D3.1 139.57,51.11 R135.2 138.68,48.55 C48.1 138.58,49.53 138.06,50.04 U6.3
OC2_DELAY_RD: length 2
  BOTTOM w0.216: R41.1 142.21,48.83 v4(141.94,49.11) 141.36,49.69 D3.3
OC2_LIMIT: length 3.1
  BOTTOM w0.216: v2(140.59,55.51) 140.39,55.71 R129.1 139.21,55.72 U16.3
OC2_OUT: length 3.4
  BOTTOM w0.216: v2(140.59,57.16) 140.06,56.64 C46.1 138.95,56.37 U16.2
OC2_RESET: length 7.2
  BOTTOM w0.216: R37.2 131.06,53.97 R131.1 ; R37.2 132.15,53.99 132.33,53.8 Q14.6 133.26,54.31 133.16,54.42 U16.5 ; R37.2 131.08,54.73 130.94,54.88 129.92,54.88 129.54,55.26 v2(129.41,55.26)
OC2_VS_R: length 16.4
  BOTTOM w0.406: C44.2 137.42,57.64 137.56,57.51 U16.1
  BOTTOM w0.508: C44.2 137.42,59.08 137.82,59.48 R22.1 139.95,59.48 v2(141.94,57.49) 141.94,54.35 141.5,53.91 140.13,53.91 138.68,52.47 R128.1
OC3_ALERT_N: length 8.7
  BOTTOM w0.216: U8.1 138.44,95.25 R140.2 137.35,95.18 Q15.3 137.35,93.93 136.83,93.41 134.34,93.41 134.13,93.21 U17.6 134.13,90.9 v2(134.49,90.54)
OC3_DELAY: length 9
  BOTTOM w0.216: U8.6 138.44,93.45 139.55,94.56 140.03,94.56 140.46,94.99 140.46,96.28 141.37,97.19 R148.1 142.21,97.42 R42.2 v2(144.27,98.08)
OC3_DELAY_N: length 7.6
  BOTTOM w0.216: v2(144.55,95.27) 142.92,95.27 142.61,94.97 142.61,93.33 142.52,93.23 142.52,93.21 142.36,93.06 142.34,93.06 142.34,93.05 141.02,93.05 140.78,93.3 U9.1 140.27,93.75 139.74,93.22 U8.4
OC3_DELAY_RC: length 6.6
  BOTTOM w0.216: v2(137.92,100.37) 137.92,100.15 D4.1 140.57,97.5 R148.2 140.57,97.39 C57.1 139.72,95.27 U8.3
OC3_DELAY_RD: length 2.9
  BOTTOM w0.216: v2(144.32,99.43) 144.2,99.56 R42.1 142.82,99.51 D4.3
OC3_LIMIT: length 3
  BOTTOM w0.216: R141.1 135.03,98.36 v2(133.88,98.36) 133.88,97.96 134.13,97.71 U17.3
OC3_OUT: length 5.1
  BOTTOM w0.216: 133.86,99.71 133.91,99.76 134.74,99.76 C55.1 ; 133.86,99.71 133.02,98.87 133.02,98.21 133.48,97.75 U17.2 ; 133.86,99.71 v2(133.86,99.7)
OC3_RESET: length 6.9
  BOTTOM w0.216: R144.1 136.53,89.68 136.09,89.24 R38.2 135.61,90.03 v2(136.4,90.82) 136.05,91.16 Q15.6 135.54,92.36 135.43,92.25 U17.5
OC3_VS_R: length 14.2
  BOTTOM w0.381: U17.1 132.83,97.64 132.56,97.91 132,97.91 C53.2 131.93,97.98 R23.1
  BOTTOM w0.508: R23.1 131.93,100.27 132.15,100.49 136.38,100.49 138.02,98.85 v2(138.02,98.21) 138.02,96.99 137.41,96.38 R140.1
OC4_ALERT_N: length 9.8
  BOTTOM w0.216: U18.6 v4(181.32,73.43) 181.91,74.02 181.91,77.32 181.08,78.16 Q16.3 179.43,78.16 R142.2 179.34,78.74 U10.1
OC4_DELAY: length 6.3
  BOTTOM w0.216: U10.6 181.62,79.25 180.85,80.02 180.85,80.56 R43.2 178.89,82.51 v4(178.38,82.51) 178.38,81.9 178.45,81.83 R149.1
OC4_DELAY_N: length 4.1
  BOTTOM w0.216: U11.1 182.08,82.09 v2(183.41,80.76) 183.2,80.55 U10.4
OC4_DELAY_RC: length 5.7
  BOTTOM w0.216: U10.3 179.83,80.53 C58.1 178.44,80.53 177.65,81.31 R149.2 177.04,81.55 176.78,81.29 v2(176.28,81.29) 176.29,81.31 D5.1
OC4_DELAY_RD: length 7.6
  BOTTOM w0.216: D5.3 177.65,83.71 177.39,83.96 177.39,85.71 177.88,86.2 v2(178.49,86.2) 179.35,85.33 179.35,84.16 179.71,83.81 R43.1
OC4_LIMIT: length 2.2
  BOTTOM w0.216: U18.3 v4(185.52,73.43) 185.73,73.43 185.77,73.47 R143.1
OC4_OUT: length 3.4
  BOTTOM w0.216: C56.1 v4(186.84,74.07) U18.2
OC4_RESET: length 11.2
  BOTTOM w0.216: R39.2 R145.1 185.34,77.26 185.33,77.26 184.93,76.86 v2(184.51,76.86) Q16.6 182.37,76.49 182.37,73.42 181.73,72.78 U18.5
OC4_VS_R: length 15.1
  TOP w0.381: v1(187.43,75.1) 186.84,75.68 184.68,75.68 182.12,78.25 v3(179.02,78.25) R142.1 v1(177.98,78.81)
  BOTTOM w0.381: R142.1 v1(177.98,78.81) ; v1(187.43,75.1) 187.4,75.12 R24.1 185.59,75.12 C54.2 185.19,74.73 U18.1
OC_ALERT_N: length 230.7
  TOP w0.216: v1(149.28,29.35) 148.76,29.35 v1(146.86,31.25) ; R13.1 116.47,18.91 116.76,18.61 119.94,18.61 v1(121.87,16.68) ; v1(149.82,62.94) 149.68,63.08 146.33,63.08 143.84,60.59 v1(143.43,60.59) ; v1(183.64,87.26) 183.64,87.42 181,90.06 154.76,90.06 v1(154.66,89.96)
  BOTTOM w0.216: v1(149.28,29.35) 150.16,28.46 150.16,20.07 150.99,19.25 150.99,16.75 150.86,16.63 147.06,16.63 R170.2 ; R6.2 183.64,85.5 v1(183.64,87.26) ; R5.2 145.2,92.24 153.24,92.24 154.66,90.82 v1(154.66,89.96) 154.66,88.86 152.12,86.31 148.55,86.31 145.91,83.67 141.39,83.67 140.39,82.67 140.39,72.38 v1(149.82,62.94) 151.7,61.06 151.7,52.71 156.3,48.11 156.3,33.52 153.84,31.07 147.04,31.07 v1(146.86,31.25) 140.33,31.25 137.64,33.94 127.69,33.94 123.61,29.85 123.61,26.44 122.15,24.98 122.15,17.11 121.87,16.83 v1(121.87,16.68) ; R172.2 R25.2 132.44,46.21 132.74,45.91 142.44,45.91 144.37,47.84 144.37,59.65 v1(143.43,60.59)
PCA9546A_ADD0: length 3.7
  TOP w0.216: U14.1 80.94,105.34 v1(80.64,105.04)
  BOTTOM w0.216: R86.1 R85.2 80.79,104.9 v1(80.64,105.04)
PCA9546A_ADD1: length 6.3
  TOP w0.216: v1(78.36,105.04) 79.83,105.04 80.42,105.63 80.59,105.63 81.05,106.09 U14.2
  BOTTOM w0.216: v1(78.36,105.04) 78.21,104.9 R81.2 R82.1
PCA9546A_ADD2: length 7.6
  TOP w0.216: v1(77.22,105.3) 77.22,107.08 76.91,107.39 U14.13
  BOTTOM w0.216: R77.2 R78.1 74.66,103.93 75.64,104.92 76.83,104.92 v1(77.22,105.3)
PCA9555_ADD0: length 3.8
  TOP w0.216: U1.21 v1(112.27,106.94)
  BOTTOM w0.216: v1(112.27,106.94) 112.78,107.45 R87.2 R88.1
PCA9555_ADD1: length 6.3
  TOP w0.216: U1.2 108.6,108.24 109.22,108.85 v1(109.22,110.12) 109.22,110.76 108.58,111.39 R84.1
  BOTTOM w0.216: v1(109.22,110.12) 108.97,110.38 R83.2
PCA9555_ADD2: length 9.1
  TOP w0.216: U1.3 108.97,107.59 109.86,108.47 109.86,111.32 v1(109.35,111.83) 109.35,111.9 108.84,112.41 R80.1
  BOTTOM w0.216: R79.2 108.92,111.39 v1(109.35,111.83)
PD_HEADER: length 7.4
  TOP w0.216: CON1.3 188.11,81.42 188.47,81.07 188.47,78.58 v3(187.86,77.97) 187.48,77.59 R61.1
PD_LM393: length 5.7
  BOTTOM w0.216: R156.1 119.74,33.08 U19.5 ; U19.5 118.96,32.97 118.77,32.78 118.77,32.53 118.98,32.32 U19.6 ; U19.5 121.58,32.97 v2(121.59,32.96)
PDB_CURRENT_ALERT_N: length 123.1
  TOP w0.216: U1.16 110.83,103.69 109.26,102.12 109.26,101.51 109.26,101.16 108.68,100.59 105.24,100.59 v1(105.23,100.6)
  BOTTOM w0.216: v1(105.23,100.6) 105.23,99.77 105.57,99.42 105.57,91.96 116.15,81.38 116.15,75.87 123.27,68.75 136.73,68.75 145.21,60.27 145.21,47.41 141.88,44.08 126.46,44.08 125.32,42.94 125.32,36.9 124.1,35.68 118.87,35.68 R169.2
PDB_CURRENT_ALERT_R_N: length 7
  BOTTOM w0.216: v2(116.48,35.4) 116.56,35.32 R169.1 R168.2 117.35,33.94 117.35,32.02 116.35,31.02 U19.1
PSU1_ALERT_BUF_N: length 1.3
  TOP w0.216: R68.1 30.23,110.77 U21.4
PSU1_ALERT_N: length 24.6
  TOP w0.216: J5.11 55.49,108.48 55.49,109.84 54.06,111.27 36.2,111.27 35.03,110.1 R62.2 34.82,109.95 34.65,110.12 U21.2
PSU1_BLADE_EN_N: length 54.5
  TOP w0.216: R72.1 21.59,102.17 24.34,104.92 65.66,104.92 66.55,105.81 66.55,107.42 J5.1
PSU1_BLADE_EN_R1_N: length 3.1
  TOP w0.216: J8.1 20.75,85.37 20.75,87.69 L1.2
PSU1_BLADE_EN_R_N: length 9.6
  TOP w0.216: R72.2 R110.2 21.83,95.41 22.2,95.04 22.2,93.86 C32.1 21.82,93.25 22.23,92.85 22.23,91.37 20.75,89.89 C136.1 v1(20.7,89.17) L1.1
PSU1_GREEN_LED: length 47.7
  TOP w0.216: J5.12 55.41,106.44 54.52,107.33 54.52,109.12 53.21,110.43 41.5,110.43 R33.1 41.29,110.46 40.84,110.01 39.26,110.01 v1(39.09,110.17)
  BOTTOM w0.216: Q20.5 18.04,99.41 18.26,99.63 18.26,102.99 24.61,109.33 36.77,109.33 37.52,110.07 38.99,110.07 v1(39.09,110.17)
PSU1_GREEN_LED_N: length 124.9
  TOP w0.216: v1(20.07,7.89) 20.49,8.31 20.49,11.46 20.87,11.84 C152.1 L24.2
  BOTTOM w0.216: v1(20.07,7.89) 19.68,8.27 19.68,11.2 15.22,15.67 1.96,15.67 1.3,16.32 1.3,91.69 4.11,94.5 17.73,94.5 18.67,95.44 18.67,96.29 R177.2
PSU1_GREEN_LED_R1_N: length 21.5
  TOP w0.216: J10.4 4.72,20.43 5.84,21.55 12.41,21.55 19.73,14.24 20.73,14.24 21.08,13.88 L24.1
PSU1_GREEN_LED_R_N: length 3.1
  BOTTOM w0.216: R177.1 18.97,97.3 v2(20.07,97.3) 20.07,98.44 19.74,98.76 Q20.3
PSU1_LR_SELECT: length 60.8
  TOP w0.216: L11.2 C146.1 19.72,89.89 20.04,90.21 20.04,91.56 20.95,92.46 20.95,102.12 21.17,102.34 21.17,102.35 24.17,105.34 64.43,105.34 J5.2
PSU1_LR_SELECT_R: length 5.3
  TOP w0.216: J8.2 19.32,83.78 19.32,87.62 L11.1
PSU1_PRESENT_N: length 58.8
  TOP w0.216: R65.1 19.68,101.73 23.7,105.76 35.45,105.76 36,106.31 v1(43.87,106.31)
  BOTTOM w0.216: v1(43.87,106.31) 43.87,107.64 47.29,111.06 59.51,111.06 60.6,109.97 60.6,106.9 61.06,106.44 J5.6
PSU1_PS_ON_N: length 32.4
  TOP w0.216: v1(46.91,106.31) 46.91,106.77 45.69,107.99 37.52,107.99 36.69,108.82 32.62,108.82 31.91,108.11 31.91,108.1 31.39,107.58 R69.2
  BOTTOM w0.216: J5.10 57.3,106.44 56.61,107.14 56.61,108.93 56.13,109.4 48.68,109.4 46.91,107.63 v1(46.91,106.31)
PSU1_THROTTLE_R: length 64.8
  TOP w0.216: C132.1 v1(15.62,89.24) L3.1
  BOTTOM w0.216: v1(15.62,89.24) 15.7,89.24 17.12,90.67 20.95,90.67 22.29,92 22.29,103.48 24.12,105.31 61.81,105.31 62.56,106.06 62.56,107.41 J5.5
PSU1_THROTTLE_R1: length 3.1
  TOP w0.216: L3.2 15.62,87.14 16.24,86.52 J8.5
PSU1_VSENSE_DN: length 25.5
  TOP w0.254: R192.1 82.65,100.4 C111.2 83.09,100.84 87.64,100.84 90.37,103.57 90.37,106.39 94.11,110.12 97.25,110.12 98.14,109.23 98.14,107.67 99.1,106.71 J21.2
PSU1_VSENSE_DP: length 24.1
  TOP w0.254: J21.1 98.71,108.44 98.52,108.64 98.52,109.39 97.4,110.5 93.95,110.5 89.99,106.55 89.99,103.73 87.48,101.22 83.09,101.22 C111.1 82.77,101.54 R191.1
PSU1_YELLOW_LED: length 43
  TOP w0.216: J5.13 52.1,109.87 47.19,109.87 47.19,109.87 42.77,109.87 41.88,108.98 R30.1 41.29,109.19 40.89,109.59 39.22,109.59 v1(39.09,109.46)
  BOTTOM w0.216: Q20.2 18.98,99.41 18.68,99.71 18.68,102.81 24.78,108.91 36.97,108.91 37.4,109.34 37.7,109.64 38.86,109.64 39.04,109.46 v1(39.09,109.46)
PSU1_YELLOW_LED_N: length 129.5
  TOP w0.216: v1(21.34,6.62) 22.63,7.91 22.63,11.7 22.49,11.84 C147.1 L21.1
  BOTTOM w0.216: R174.1 18,96.55 18.21,96.33 18.21,95.59 17.54,94.92 3.94,94.92 0.88,91.87 0.88,16.15 1.79,15.25 15.05,15.25 17.58,12.72 17.58,8.92 19.88,6.62 v1(21.34,6.62)
PSU1_YELLOW_LED_R1_N: length 26.6
  TOP w0.216: J10.3 4.72,17.62 3.8,18.54 3.8,21.05 4.72,21.97 12.59,21.97 19.81,14.75 21.36,14.75 22.1,14.01 L21.2
PSU1_YELLOW_LED_R_N: length 4.5
  BOTTOM w0.216: R174.2 v2(16.69,97.35) 16.69,99.68 17.06,100.06 Q20.6
PSU2_ALERT_BUF_N: length 1.2
  TOP w0.216: R186.1 68.93,2.57 U22.4
PSU2_ALERT_N: length 37.9
  TOP w0.216: U22.2 66.07,3.22 66.29,3.44 66.29,4.82 R63.2 65.15,4.84 63.75,3.44 v1(63.63,3.44)
  BOTTOM w0.216: v1(63.63,3.44) 63.7,3.37 65.33,3.37 72.21,10.25 72.21,19.65 68.6,23.26 68.6,25.85 67.9,26.55 66.61,26.55 65.53,27.63 J6.11
PSU2_ALERT_R_N: length 24.1
  TOP w0.216: L10.2 20.05,106.5 13.69,100.14 10.54,100.14 v1(9.98,99.58)
  BOTTOM w0.216: v1(9.98,99.58) 9.7,99.86 3.56,99.86 J9.7
PSU2_BLADE_EN_N: length 6
  TOP w0.216: J6.1 75.52,28.5 73.12,30.9 R73.1
PSU2_BLADE_EN_R_N: length 296.1
  TOP w0.216: R73.2 C31.1 70.17,31.7 69.6,31.13 69.6,29.35 70.48,28.46 70.48,24.78 v1(67.06,21.35) ; v1(110.92,102.38) 111.66,101.64 U1.13
  VCC1 w0.213: v1(105.36,108.35) 104.52,108.35 99.84,103.66 97.86,103.66 96.91,102.71 96.91,100.3 95.93,99.31 84.32,99.31 79.52,104.11 76.72,104.11 75.06,105.77 69.39,105.77 68.19,104.57 24.43,104.57 22.35,102.49 22.35,91.96 19.23,88.84 19.23,81.88 18.5,81.15 16.1,81.15 11.38,76.43 11.38,70.2 7.75,66.56 v1(7.06,66.56)
  BOTTOM w0.216: v1(105.36,108.35) 105.87,107.84 106.53,107.84 109.5,104.86 109.5,104.4 110.92,102.99 v1(110.92,102.38) 110.72,102.38 R111.2 ; v1(7.06,66.56) 5.12,66.56 2.6,64.05 2.6,24.84 6.28,21.16 11.51,21.16 21.95,10.72 21.95,8.41 23.94,6.42 33.25,6.42 33.81,5.86 43.05,5.86 44.32,4.59 48.39,4.59 50.42,6.62 64.52,6.62 65.43,7.54 65.43,20.62 66.17,21.35 v1(67.06,21.35)
